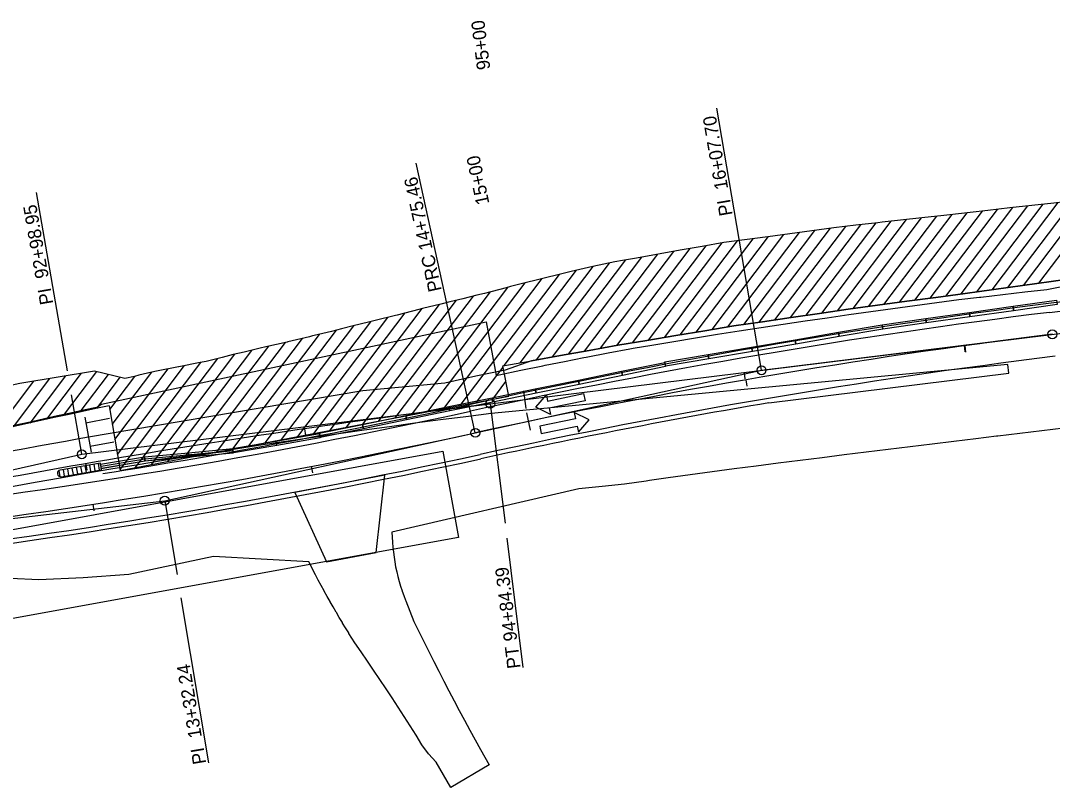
# Model space of a CAD drawing. Extents: x 1568809 to 1572786, y 728326 to 734907.
# Drawn here: x 1569562.7 to 1570028.4, y 731945.8 to 732292 of the extents above; entities that cross this region are included whole.
import ezdxf

# ---------------------------------------------------------------- set-up
doc = ezdxf.new("R2010")
doc.units = 0
for name, color, linetype in [('R_Horz Alg', 7, 'Continuous'), ('R_Horz Alg Annot', 7, 'Continuous'), ('R_MOT', 7, 'Continuous'), ('R_No Plot', 7, 'Continuous'), ('R_Striping', 7, 'Continuous')]:
    doc.layers.add(name, color=color, linetype=linetype)

msp = doc.modelspace()

# ---------------------------------------------------------------- linework, layer by layer
at = {"layer": 'R_Horz Alg'}
msp.add_line((1569774.69, 732119.01), (1571082.41, 732280.73), dxfattribs=at)
for centre, radius, start, end in [((1570379.97, 729307.25), 2864.79, 97.05, 102.33591), ((1570243.51, 728328.17), 3819.72, 97.05, 102.61775), ((1569155.89, 734904.54), 2864.79, 276.60226, 282.33591)]:
    msp.add_arc(centre, radius, start, end, dxfattribs=at)
at = {"layer": 'R_Horz Alg Annot'}
for p, q in [((1569897.12, 732134.15), (1570028.36, 732150.38)), ((1569767.93, 732105.9), (1569897.12, 732134.15)), ((1569590.36, 732096.21), (1569774.69, 732119.01)), ((1569627.78, 732075.25), (1569767.93, 732105.9)), ((1569409.1, 732055.64), (1569590.36, 732096.21)), ((1569485.27, 732058.75), (1569627.78, 732075.25))]:
    msp.add_line(p, q, dxfattribs=at)
for points in [[(1569897.12, 732134.15), (1569876.92, 732252.44)], [(1569767.93, 732105.9), (1569741.31, 732227.64)], [(1569583.83, 732133.85), (1569569.86, 732214.45)], [(1569989.03, 732142.49), (1569988.67, 732145.47)], [(1569989.36, 732142.25), (1569988.95, 732145.23)], [(1569889.79, 732130.22), (1569889.42, 732133.2)], [(1569890.65, 732126.9), (1569890.14, 732129.85)], [(1569789.69, 732124.89), (1569790.67, 732116.95)], [(1569590.36, 732096.21), (1569585.7, 732123.06)], [(1569774.69, 732119.01), (1569781.36, 732065.06)], [(1569791.11, 732114.95), (1569792.75, 732107.12)], [(1569691.49, 732104.76), (1569691.05, 732107.72)], [(1569592.82, 732089.01), (1569592.31, 732091.97)], [(1569694.58, 732087.8), (1569694.01, 732090.75)], [(1569595.95, 732070.72), (1569595.49, 732073.68)], [(1569627.78, 732075.25), (1569633.33, 732041.97)], [(1569782.19, 732058.34), (1569789.42, 731999.91)], [(1569635.1, 732031.35), (1569647.53, 731956.88)]]:
    msp.add_lwpolyline(points, dxfattribs=at)
for centre in [(1570028.36, 732150.38), (1569897.12, 732134.15), (1569774.69, 732119.01), (1569767.93, 732105.9), (1569590.36, 732096.21), (1569627.78, 732075.25)]:
    msp.add_circle(centre, 2, dxfattribs=at)
at = {"layer": 'R_MOT'}
for p, q in [((1570582.65, 732233.03), (1570026.64, 732164.27)), ((1570022.29, 732173.47), (1570052.02, 732212.78)), ((1569980.27, 732167.65), (1570010.48, 732207.58)), ((1569987.25, 732168.59), (1570017.33, 732208.35)), ((1569994.25, 732169.56), (1570024.18, 732209.12)), ((1570001.26, 732170.54), (1570031.04, 732209.91)), ((1570008.27, 732171.51), (1570037.93, 732210.73)), ((1570015.28, 732172.49), (1570044.97, 732211.73)), ((1569938.41, 732162.04), (1569969.37, 732202.97)), ((1569945.38, 732162.97), (1569976.22, 732203.74)), ((1569952.36, 732163.91), (1569983.07, 732204.5)), ((1569959.34, 732164.85), (1569989.92, 732205.27)), ((1569966.32, 732165.78), (1569996.77, 732206.04)), ((1569973.29, 732166.72), (1570003.63, 732206.81)), ((1569896.11, 732155.86), (1569928.2, 732198.27)), ((1569903.16, 732156.89), (1569935.1, 732199.1)), ((1569910.22, 732157.93), (1569941.96, 732199.89)), ((1569917.27, 732158.96), (1569948.81, 732200.66)), ((1569924.32, 732160), (1569955.66, 732201.43)), ((1569931.38, 732161.03), (1569962.52, 732202.2)), ((1569860.45, 732150.15), (1569893.28, 732193.54)), ((1569867.62, 732151.34), (1569900.26, 732194.49)), ((1569874.79, 732152.53), (1569907.24, 732195.44)), ((1569881.96, 732153.73), (1569914.23, 732196.38)), ((1569889.06, 732154.82), (1569921.21, 732197.33)), ((1569831.75, 732145.37), (1569864.83, 732189.09)), ((1569838.93, 732146.57), (1569872.06, 732190.37)), ((1569846.1, 732147.76), (1569879.28, 732191.62)), ((1569853.28, 732148.96), (1569886.29, 732192.6)), ((1569809.99, 732141.46), (1569843.09, 732185.22)), ((1569817.25, 732142.77), (1569850.34, 732186.51)), ((1569824.5, 732144.07), (1569857.58, 732187.8)), ((1569788.23, 732137.56), (1569821.14, 732181.07)), ((1569795.48, 732138.86), (1569828.55, 732182.58)), ((1569802.74, 732140.16), (1569835.85, 732183.94)), ((1569753.8, 732116.91), (1569798.16, 732175.55)), ((1569761.13, 732118.31), (1569805.88, 732177.46)), ((1569780.98, 732136.26), (1569813.54, 732179.31)), ((1569739.13, 732114.09), (1569782.62, 732171.58)), ((1569746.46, 732115.5), (1569790.41, 732173.6)), ((1569717.12, 732109.87), (1569759.42, 732165.77)), ((1569724.46, 732111.28), (1569767.09, 732167.63)), ((1569731.79, 732112.68), (1569774.81, 732169.55)), ((1569702.46, 732107.05), (1569744.01, 732161.98)), ((1569709.79, 732108.46), (1569751.72, 732163.88)), ((1569687.79, 732104.24), (1569728.49, 732158.05)), ((1569695.12, 732105.65), (1569736.25, 732160.02)), ((1569665.78, 732100.02), (1569705.3, 732152.25)), ((1569673.12, 732101.42), (1569713.09, 732154.27)), ((1569680.45, 732102.83), (1569720.72, 732156.06)), ((1569651.12, 732097.2), (1569689.94, 732148.53)), ((1569658.45, 732098.61), (1569697.61, 732150.37)), ((1569629.11, 732092.98), (1569667.06, 732143.14)), ((1569636.45, 732094.39), (1569674.73, 732144.99)), ((1569643.78, 732095.79), (1569682.29, 732146.7)), ((1569607.59, 732089.39), (1569644.14, 732137.71)), ((1569614.44, 732090.16), (1569651.76, 732139.49)), ((1569621.78, 732091.57), (1569659.46, 732141.38)), ((1569582.07, 732113.67), (1569597.09, 732133.52)), ((1569604.12, 732109.66), (1569622, 732133.3)), ((1569605.27, 732102.9), (1569629.39, 732134.78)), ((1569606.43, 732096.15), (1569636.76, 732136.24)), ((1569768.47, 732119.72), (1569780.45, 732135.56)), ((1569551.89, 732106.92), (1569568.76, 732129.23)), ((1569559.46, 732108.64), (1569575.93, 732130.41)), ((1569567.01, 732110.33), (1569583.1, 732131.6)), ((1569574.55, 732112.01), (1569590.27, 732132.79)), ((1569589.58, 732115.31), (1569602.39, 732132.24)), ((1569597.07, 732116.92), (1569607.69, 732130.97)), ((1569602.96, 732116.42), (1569614.21, 732131.29)), ((1569775.8, 732121.13), (1569781.78, 732129.04)), ((1569591.68, 732112.93), (1569594.6, 732097.2)), ((1569602.9, 732112.33), (1569592.16, 732110.33)), ((1569604.88, 732101.65), (1569594.14, 732099.66)), ((1569658.58, 732097.77), (1569618.75, 732094.03)), ((1569658.55, 732097.8), (1569618.83, 732093.07)), ((1569594.41, 732088.39), (1569593.9, 732091.35)), ((1569596.38, 732088.73), (1569595.88, 732091.69)), ((1569598.35, 732089.07), (1569597.85, 732092.02)), ((1569618.75, 732094.03), (1569599.03, 732090.7)), ((1569618.83, 732093.07), (1569599.13, 732089.62)), ((1569580.6, 732086.09), (1569580.12, 732088.92)), ((1569582.58, 732086.37), (1569582.08, 732089.32)), ((1569584.55, 732086.7), (1569584.05, 732089.66)), ((1569586.53, 732087.04), (1569586.02, 732090)), ((1569588.5, 732087.38), (1569587.99, 732090.33)), ((1569590.47, 732087.72), (1569589.96, 732090.67)), ((1569592.44, 732088.05), (1569591.93, 732091.01))]:
    msp.add_line(p, q, dxfattribs=at)
for points in [[(1570010.6, 732163.02), (1570030.3, 732165.79), (1570030.58, 732163.82), (1570010.88, 732161.05)], [(1569990.9, 732160.26), (1570010.6, 732163.02), (1570010.88, 732161.05), (1569991.18, 732158.29)], [(1569951.5, 732154.72), (1569971.2, 732157.49), (1569971.48, 732155.52), (1569951.78, 732152.75)], [(1569971.2, 732157.49), (1569990.9, 732160.26), (1569991.18, 732158.29), (1569971.48, 732155.52)], [(1569931.87, 732151.31), (1569951.48, 732154.65), (1569951.82, 732152.69), (1569932.21, 732149.34)], [(1569892.65, 732144.61), (1569912.26, 732147.96), (1569912.6, 732146), (1569892.99, 732142.65)], [(1569912.26, 732147.96), (1569931.87, 732151.31), (1569932.21, 732149.34), (1569912.6, 732146)], [(1569873.04, 732141.26), (1569892.65, 732144.61), (1569892.99, 732142.65), (1569873.38, 732139.3)], [(1569833.95, 732133.73), (1569853.43, 732137.73), (1569853.83, 732135.78), (1569834.35, 732131.78)], [(1569853.43, 732137.92), (1569873.04, 732141.26), (1569873.38, 732139.3), (1569853.77, 732135.96)], [(1569814.46, 732129.73), (1569833.95, 732133.73), (1569834.35, 732131.78), (1569814.86, 732127.78)], [(1569794.97, 732125.73), (1569814.46, 732129.73), (1569814.86, 732127.78), (1569795.37, 732123.78)], [(1569775.48, 732121.73), (1569794.97, 732125.73), (1569795.37, 732123.78), (1569775.88, 732119.78)], [(1569756, 732117.73), (1569775.48, 732121.73), (1569775.88, 732119.78), (1569756.4, 732115.78)], [(1569801.85, 732114.22), (1569795.21, 732117.42), (1569800, 732123.02), (1569800.58, 732120.27), (1569816.77, 732123.67), (1569817.47, 732120.37), (1569801.27, 732116.97)], [(1569736.51, 732113.73), (1569756, 732117.73), (1569756.4, 732115.78), (1569736.91, 732111.78)], [(1569814.47, 732106.21), (1569819.26, 732111.82), (1569812.62, 732115.02), (1569813.2, 732112.27), (1569797, 732108.87), (1569797.69, 732105.57), (1569813.89, 732108.97)], [(1569697.54, 732105.72), (1569717.02, 732109.73), (1569717.42, 732107.78), (1569697.94, 732103.78)], [(1569717.02, 732109.73), (1569736.51, 732113.73), (1569736.91, 732111.78), (1569717.42, 732107.78)], [(1569677.99, 732102.19), (1569697.59, 732105.62), (1569697.93, 732103.66), (1569678.33, 732100.23)], [(1569658.39, 732098.77), (1569677.99, 732102.19), (1569678.33, 732100.23), (1569658.74, 732096.81)], [(1569638.76, 732094.91), (1569618.85, 732093.03), (1569618.66, 732095.02), (1569638.57, 732096.9)], [(1569658.67, 732096.78), (1569638.76, 732094.91), (1569638.57, 732096.9), (1569658.48, 732098.77)], [(1569618.92, 732093.04), (1569599.2, 732089.72), (1569598.86, 732091.69), (1569618.59, 732095.01)]]:
    msp.add_lwpolyline(points, close=True, dxfattribs=at)
msp.add_lwpolyline([(1569581.05, 732086.1), (1569599.28, 732089.22), (1569598.78, 732092.18), (1569580.54, 732089.06)], dxfattribs=at)
for centre, radius, start, end in [((1570390.66, 729309.08), 2878.31, 97.26562, 102.55153), ((1569155.89, 734904.54), 2851.79, 278.95456, 282.33591), ((1569580.8, 732087.58), 1.5, 99.7168, 279.7168)]:
    msp.add_arc(centre, radius, start, end, dxfattribs=at)
at = {"layer": 'R_No Plot'}
for p, q in [((1570582.65, 732233.03), (1570026.64, 732164.27)), ((1569979.4, 732204.09), (1569969.46, 732202.98)), ((1569979.4, 732204.09), (1569969.46, 732202.98)), ((1569979.4, 732204.09), (1569969.46, 732202.98)), ((1569899.98, 732194.45), (1569880.16, 732191.77)), ((1569899.98, 732194.45), (1569880.16, 732191.77)), ((1569899.98, 732194.45), (1569880.16, 732191.77)), ((1569860.44, 732188.31), (1569840.72, 732184.8)), ((1569860.44, 732188.31), (1569840.72, 732184.8)), ((1569860.44, 732188.31), (1569840.72, 732184.8)), ((1569599.2, 732118.84), (1569772.9, 732155.99)), ((1569772.9, 732155.99), (1569777.36, 732131.86)), ((1570008.21, 732136.8), (1569775.13, 732114.63)), ((1570008.7, 732132.83), (1570008.21, 732136.8)), ((1569900.4, 732119.44), (1570008.7, 732132.83)), ((1569607.68, 732088.86), (1569783.11, 732122.53)), ((1569607.68, 732088.86), (1569783.11, 732122.53)), ((1569607.68, 732088.86), (1569783.11, 732122.53)), ((1569596.97, 732117.38), (1569599.2, 732118.84)), ((1569602.67, 732118.12), (1569607.68, 732088.86)), ((1569602.67, 732118.12), (1569607.68, 732088.86)), ((1569602.67, 732118.12), (1569607.68, 732088.86)), ((1569601.29, 732105.28), (1569601.29, 732105.28)), ((1569601.29, 732105.28), (1569601.29, 732105.28)), ((1569814.7, 732080.55), (1569730.27, 732061.11)), ((1569774.18, 731955.95), (1569756.95, 731945.81))]:
    msp.add_line(p, q, dxfattribs=at)
for points in [[(1570088.5, 732218.16), (1570078.6, 732216.7), (1570068.71, 732215.24), (1570058.81, 732213.78), (1570048.92, 732212.32), (1570039.02, 732210.86), (1570029.09, 732209.67), (1570019.15, 732208.56), (1570009.21, 732207.44), (1569999.28, 732206.32)], [(1570088.5, 732218.16), (1570078.6, 732216.7), (1570068.71, 732215.24), (1570058.81, 732213.78), (1570048.92, 732212.32), (1570039.02, 732210.86), (1570029.09, 732209.67), (1570019.15, 732208.56), (1570009.21, 732207.44), (1569999.28, 732206.32)], [(1570088.5, 732218.16), (1570078.6, 732216.7), (1570068.71, 732215.24), (1570058.81, 732213.78), (1570048.92, 732212.32), (1570039.02, 732210.86), (1570029.09, 732209.67), (1570019.15, 732208.56), (1570009.21, 732207.44), (1569999.28, 732206.32)], [(1569969.46, 732202.98), (1569951.57, 732200.97), (1569949.59, 732200.74)], [(1569969.46, 732202.98), (1569951.57, 732200.97), (1569949.59, 732200.74)], [(1569969.46, 732202.98), (1569951.57, 732200.97), (1569949.59, 732200.74)], [(1569999.28, 732206.32), (1569991.33, 732205.43), (1569982.07, 732204.39), (1569979.4, 732204.09)], [(1569999.28, 732206.32), (1569991.33, 732205.43), (1569982.07, 732204.39), (1569979.4, 732204.09)], [(1569999.28, 732206.32), (1569991.33, 732205.43), (1569982.07, 732204.39), (1569979.4, 732204.09)], [(1569949.59, 732200.74), (1569939.65, 732199.63), (1569929.71, 732198.48), (1569919.8, 732197.14), (1569909.89, 732195.79), (1569899.98, 732194.45)], [(1569949.59, 732200.74), (1569939.65, 732199.63), (1569929.71, 732198.48), (1569919.8, 732197.14), (1569909.89, 732195.79), (1569899.98, 732194.45)], [(1569949.59, 732200.74), (1569939.65, 732199.63), (1569929.71, 732198.48), (1569919.8, 732197.14), (1569909.89, 732195.79), (1569899.98, 732194.45)], [(1569880.16, 732191.77), (1569870.3, 732190.06), (1569860.44, 732188.31)], [(1569880.16, 732191.77), (1569870.3, 732190.06), (1569860.44, 732188.31)], [(1569880.16, 732191.77), (1569870.3, 732190.06), (1569860.44, 732188.31)], [(1569840.72, 732184.8), (1569834.31, 732183.66), (1569830.86, 732183.05), (1569821.03, 732181.05), (1569811.24, 732178.77), (1569803.41, 732176.86), (1569801.46, 732176.38), (1569794.78, 732174.71), (1569791.68, 732173.92), (1569783.87, 732171.91), (1569781.92, 732171.4), (1569772.16, 732168.86), (1569768.63, 732168.01), (1569762.3, 732166.47), (1569756.37, 732165.04), (1569752.39, 732164.05), (1569744.13, 732162.01), (1569742.5, 732161.6), (1569732.63, 732159.1), (1569731.91, 732158.92), (1569722.76, 732156.58), (1569719.7, 732155.8), (1569712.87, 732154.22), (1569707.49, 732152.82), (1569703.02, 732151.65), (1569695.28, 732149.82), (1569694.52, 732149.63), (1569693.15, 732149.3), (1569683.28, 732146.92), (1569683.07, 732146.88), (1569673.4, 732144.69), (1569670.85, 732144.06), (1569663.55, 732142.29), (1569658.64, 732141.2), (1569653.69, 732139.97), (1569646.47, 732138.18), (1569643.83, 732137.65), (1569634.21, 732135.73), (1569633.92, 732135.68), (1569624.01, 732133.72), (1569621.95, 732133.29), (1569616.11, 732131.99), (1569614.18, 732131.28), (1569609.76, 732130.47)], [(1569840.72, 732184.8), (1569834.31, 732183.66), (1569830.86, 732183.05), (1569821.03, 732181.05), (1569811.24, 732178.77), (1569803.41, 732176.86), (1569801.46, 732176.38), (1569794.78, 732174.71), (1569791.68, 732173.92), (1569783.87, 732171.91), (1569781.92, 732171.4), (1569772.16, 732168.86), (1569768.63, 732168.01), (1569762.3, 732166.47), (1569756.37, 732165.04), (1569752.39, 732164.05), (1569744.13, 732162.01), (1569742.5, 732161.6), (1569732.63, 732159.1), (1569731.91, 732158.92), (1569722.76, 732156.58), (1569719.7, 732155.8), (1569712.87, 732154.22), (1569707.49, 732152.82), (1569703.02, 732151.65), (1569695.28, 732149.82), (1569694.52, 732149.63), (1569693.15, 732149.3), (1569683.28, 732146.92), (1569683.07, 732146.88), (1569673.4, 732144.69), (1569670.85, 732144.06), (1569663.55, 732142.29), (1569658.64, 732141.2), (1569653.69, 732139.97), (1569646.47, 732138.18), (1569643.83, 732137.65), (1569634.21, 732135.73), (1569633.92, 732135.68), (1569624.01, 732133.72), (1569621.95, 732133.29), (1569616.11, 732131.99), (1569614.18, 732131.28), (1569609.76, 732130.47)], [(1569840.72, 732184.8), (1569834.31, 732183.66), (1569830.86, 732183.05), (1569821.03, 732181.05), (1569811.24, 732178.77), (1569803.41, 732176.86), (1569801.46, 732176.38), (1569794.78, 732174.71), (1569791.68, 732173.92), (1569783.87, 732171.91), (1569781.92, 732171.4), (1569772.16, 732168.86), (1569768.63, 732168.01), (1569762.3, 732166.47), (1569756.37, 732165.04), (1569752.39, 732164.05), (1569744.13, 732162.01), (1569742.5, 732161.6), (1569732.63, 732159.1), (1569731.91, 732158.92), (1569722.76, 732156.58), (1569719.7, 732155.8), (1569712.87, 732154.22), (1569707.49, 732152.82), (1569703.02, 732151.65), (1569695.28, 732149.82), (1569694.52, 732149.63), (1569693.15, 732149.3), (1569683.28, 732146.92), (1569683.07, 732146.88), (1569673.4, 732144.69), (1569670.85, 732144.06), (1569663.55, 732142.29), (1569658.64, 732141.2), (1569653.69, 732139.97), (1569646.47, 732138.18), (1569643.83, 732137.65), (1569634.21, 732135.73), (1569633.92, 732135.68), (1569624.01, 732133.72), (1569621.95, 732133.29), (1569616.11, 732131.99), (1569614.18, 732131.28), (1569609.76, 732130.47)], [(1570040.82, 732176.05), (1570027.86, 732174.24), (1570014.9, 732172.44), (1570001.94, 732170.63), (1569988.99, 732168.82), (1569975.8, 732167.05), (1569962.62, 732165.29), (1569949.43, 732163.52), (1569936.25, 732161.75), (1569923.33, 732159.85), (1569910.41, 732157.95), (1569897.49, 732156.06), (1569884.56, 732154.16), (1569871.51, 732151.99), (1569858.45, 732149.82), (1569845.39, 732147.64), (1569832.33, 732145.47), (1569819.33, 732143.14), (1569806.33, 732140.81), (1569793.33, 732138.48), (1569781.46, 732134.16), (1569768.14, 732131.46), (1569754.19, 732128.31), (1569717.2, 732124.92), (1569601.29, 732105.28)], [(1570040.82, 732176.05), (1570027.86, 732174.24), (1570014.9, 732172.44), (1570001.94, 732170.63), (1569988.99, 732168.82), (1569975.8, 732167.05), (1569962.62, 732165.29), (1569949.43, 732163.52), (1569936.25, 732161.75), (1569923.33, 732159.85), (1569910.41, 732157.95), (1569897.49, 732156.06), (1569884.56, 732154.16), (1569871.51, 732151.99), (1569858.45, 732149.82), (1569845.39, 732147.64), (1569832.33, 732145.47), (1569819.33, 732143.14), (1569806.33, 732140.81), (1569793.33, 732138.48), (1569781.46, 732134.16), (1569768.14, 732131.46), (1569754.19, 732128.31), (1569717.2, 732124.92), (1569601.29, 732105.28)], [(1569793.33, 732138.48), (1569806.33, 732140.81), (1569819.33, 732143.14), (1569832.33, 732145.47), (1569845.39, 732147.64), (1569858.45, 732149.82), (1569871.51, 732151.99), (1569884.56, 732154.16), (1569897.49, 732156.06), (1569910.41, 732157.95), (1569923.33, 732159.85), (1569936.25, 732161.75), (1569949.43, 732163.52), (1569962.62, 732165.29), (1569975.8, 732167.05), (1569988.99, 732168.82), (1570001.94, 732170.63), (1570014.9, 732172.44), (1570027.86, 732174.24), (1570040.82, 732176.05)], [(1569793.33, 732138.48), (1569806.33, 732140.81), (1569819.33, 732143.14), (1569832.33, 732145.47), (1569845.39, 732147.64), (1569858.45, 732149.82), (1569871.51, 732151.99), (1569884.56, 732154.16), (1569897.49, 732156.06), (1569910.41, 732157.95), (1569923.33, 732159.85), (1569936.25, 732161.75), (1569949.43, 732163.52), (1569962.62, 732165.29), (1569975.8, 732167.05), (1569988.99, 732168.82), (1570001.94, 732170.63), (1570014.9, 732172.44), (1570027.86, 732174.24), (1570040.82, 732176.05)], [(1569793.33, 732138.48), (1569806.33, 732140.81), (1569819.33, 732143.14), (1569832.33, 732145.47), (1569845.39, 732147.64), (1569858.45, 732149.82), (1569871.51, 732151.99), (1569884.56, 732154.16), (1569897.49, 732156.06), (1569910.41, 732157.95), (1569923.33, 732159.85), (1569936.25, 732161.75), (1569949.43, 732163.52), (1569962.62, 732165.29), (1569975.8, 732167.05), (1569988.99, 732168.82), (1570001.94, 732170.63), (1570014.9, 732172.44), (1570027.86, 732174.24), (1570040.82, 732176.05)], [(1569777.36, 732131.86), (1569778.71, 732132.16), (1569788.54, 732134.2), (1569798.36, 732136.2), (1569799.52, 732136.43), (1569808.2, 732138.16), (1569816.86, 732139.87), (1569818.03, 732140.1), (1569827.87, 732142.02), (1569837.73, 732143.82), (1569839.2, 732144.08), (1569847.59, 732145.5), (1569857.46, 732147.17), (1569867.34, 732148.82), (1569877.21, 732150.43), (1569887.09, 732152.02), (1569896.98, 732153.53), (1569906.88, 732155), (1569916.77, 732156.47), (1569926.67, 732157.89), (1569936.57, 732159.31), (1569946.48, 732160.7), (1569956.38, 732162.11), (1569966.29, 732163.45), (1569976.2, 732164.81), (1569986.11, 732166.13), (1569995.44, 732167.22), (1569996.06, 732167.15), (1570005.99, 732168.34), (1570015.92, 732169.51), (1570025.85, 732170.67), (1570035.69, 732172.64)], [(1569783.11, 732122.53), (1569780.33, 732136.14), (1569793.33, 732138.48)], [(1569783.11, 732122.53), (1569780.33, 732136.14), (1569793.33, 732138.48)], [(1569783.11, 732122.53), (1569780.33, 732136.14), (1569793.33, 732138.48)], [(1569609.76, 732130.47), (1569596.09, 732133.76), (1569562.31, 732128.16), (1569491.86, 732112.75)], [(1569609.76, 732130.47), (1569596.09, 732133.76), (1569562.31, 732128.16), (1569491.86, 732112.75)], [(1569609.76, 732130.47), (1569596.09, 732133.76), (1569562.31, 732128.16), (1569491.86, 732112.75)], [(1570033.6, 732108.05), (1570023.67, 732106.82), (1570013.75, 732105.61), (1570003.82, 732104.42), (1570003.21, 732104.35), (1569993.89, 732103.2), (1569983.97, 732101.96), (1569974.05, 732100.71), (1569964.12, 732099.54), (1569954.19, 732098.34), (1569944.26, 732097.13), (1569934.34, 732095.89), (1569924.42, 732094.62), (1569914.5, 732093.37), (1569904.58, 732092.13), (1569894.66, 732090.86), (1569884.74, 732089.58), (1569874.82, 732088.29), (1569864.91, 732086.95), (1569855.01, 732085.54), (1569846.59, 732084.33), (1569845.11, 732084.12), (1569835.21, 732082.66), (1569825.26, 732081.67), (1569814.7, 732080.55)], [(1569730.27, 732061.11), (1569730.52, 732056.51), (1569730.53, 732056.42), (1569730.73, 732054.21), (1569730.98, 732052.04), (1569730.98, 732052), (1569731.29, 732049.8), (1569731.62, 732047.59), (1569731.62, 732047.58), (1569731.99, 732045.37), (1569732.47, 732043.19), (1569732.48, 732043.12), (1569733, 732041.01), (1569733.58, 732038.84), (1569733.61, 732038.72), (1569734.21, 732036.68), (1569734.9, 732034.53), (1569734.95, 732034.37), (1569735.63, 732032.39), (1569736.42, 732030.27), (1569736.51, 732030.05), (1569738.39, 732025.36), (1569740.25, 732020.66), (1569742.42, 732016.15), (1569744.67, 732011.67), (1569746.9, 732007.18), (1569749.16, 732002.72), (1569751.46, 731998.27), (1569753.74, 731993.81), (1569756.04, 731989.37), (1569758.36, 731984.93), (1569760.7, 731980.51), (1569763.06, 731976.1), (1569765.44, 731971.71), (1569767.86, 731967.33), (1569770.26, 731962.94), (1569774.18, 731955.95)], [(1569692.82, 732047.58), (1569649.72, 732050.12), (1569611.57, 732041.99), (1569590.97, 732040.46), (1569570.96, 732039.46), (1569532.47, 732041.3)], [(1569756.95, 731945.81), (1569750.25, 731957.21), (1569746.79, 731960.99), (1569743.85, 731965.06), (1569741.2, 731969.31), (1569738.56, 731973.56), (1569735.86, 731977.78), (1569733.14, 731981.98), (1569730.4, 731986.17), (1569727.65, 731990.36), (1569724.87, 731994.53), (1569722.06, 731998.68), (1569719.24, 732002.82), (1569716.41, 732006.97), (1569713.63, 732011.14), (1569710.93, 732015.35), (1569710.8, 732015.56), (1569709.37, 732017.87), (1569708.06, 732020.03), (1569707.95, 732020.21), (1569706.55, 732022.55), (1569705.24, 732024.79), (1569705.17, 732024.92), (1569703.8, 732027.29), (1569702.47, 732029.61), (1569702.43, 732029.68), (1569701.07, 732032.07), (1569699.72, 732034.47), (1569699.72, 732034.49), (1569698.38, 732036.92), (1569697.06, 732039.36), (1569697.03, 732039.41), (1569695.75, 732041.83), (1569694.47, 732044.32), (1569694.42, 732044.42), (1569692.82, 732047.58)]]:
    msp.add_lwpolyline(points, dxfattribs=at)
for points in [[(1569361.7, 732026.33), (1569753.23, 732097.58), (1569760.32, 732058.65), (1569368.79, 731987.39)], [(1569686.46, 732078.9), (1569700.8, 732047.66), (1569723.22, 732051.87), (1569727.16, 732086.85)]]:
    msp.add_lwpolyline(points, close=True, dxfattribs=at)
for centre, radius, start, end in [((1570390.66, 729309.08), 2878.31, 97.26562, 102.55153), ((1570379.97, 729307.25), 2852.79, 99.67786, 102.33591), ((1570242.6, 728334.71), 3808.72, 97.05, 102.61775), ((1570398.03, 728391.24), 3810.81, 102.04699, 105.01357), ((1570398.03, 728391.24), 3810.81, 102.04699, 105.01357), ((1570398.03, 728391.24), 3810.81, 102.04699, 105.01357), ((1570380.82, 728500.81), 3700.54, 102.22905, 105.19563), ((1569155.89, 734904.54), 2851.79, 278.95456, 282.33591), ((1570255.23, 728328.47), 3833, 99.82313, 102.78971), ((1570255.23, 728328.47), 3833, 99.82313, 102.78971), ((1569155.89, 734904.54), 2876.79, 276.60226, 282.33592)]:
    msp.add_arc(centre, radius, start, end, dxfattribs=at)
at = {"layer": 'R_Striping'}
msp.add_line((1570027.14, 732160.3), (1571081.18, 732290.66), dxfattribs=at)
for centre, radius, start, end in [((1570379.97, 729307.25), 2874.79, 97.05, 102.33591), ((1570379.97, 729307.25), 2874.79, 97.05, 102.33591), ((1570379.97, 729307.25), 2864.79, 97.05, 102.33591), ((1570379.97, 729307.25), 2854.79, 97.05, 102.33591), ((1569155.89, 734904.54), 2854.79, 276.60226, 282.33591), ((1569155.89, 734904.54), 2854.79, 276.60226, 282.33591), ((1569155.89, 734904.54), 2864.79, 276.60226, 282.33591), ((1569155.89, 734904.54), 2874.79, 276.60226, 282.33591)]:
    msp.add_arc(centre, radius, start, end, dxfattribs=at)

# ---------------------------------------------------------------- texts
at = {"layer": 'R_Horz Alg Annot'}
for s, rotation, p in [('95+00', 97.05, (1569774.74, 732270.16)), ('PI  16+07.70', 99.693, (1569884.12, 732204.35)), ('15+00', 101.845, (1569774.34, 732209.52)), ('PRC 14+75.46', 102.3359, (1569752.82, 732170.3)), ('PI  92+98.95', 99.8339, (1569577.54, 732164.28)), ('PT 94+84.39', 97.05, (1569788.43, 731999.79)), ('PI  13+32.24', 99.4691, (1569646.54, 731956.72))]:
    msp.add_text(s, height=6, rotation=rotation, dxfattribs=at).set_placement(p)

doc.saveas('drawing.dxf')
